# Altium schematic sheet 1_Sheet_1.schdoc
size 302 x 215 mm; Name: A_A4; Symbol: A_A4; Device: A_A4; @Project Name: BLDC_Feb25_uC; REV: 1.0; Date: 2024-06-12; Sheet: 1/1; Draw By: tabahi; Company: github.com/tabahi/eBike-Controller; Convert to PCB: yes; Add into BOM: yes; @Page No: 1; @Page Count: 1; @Schematic Name: mosfets_drive_uC; @Board Name: MOSFETS_drive; @Update Date: 2025-04-16; @Create Time: 07:37:43; @Update Time: 03:45:01; @Page Name: Sheet_1; @Create Date: 2025-02-03
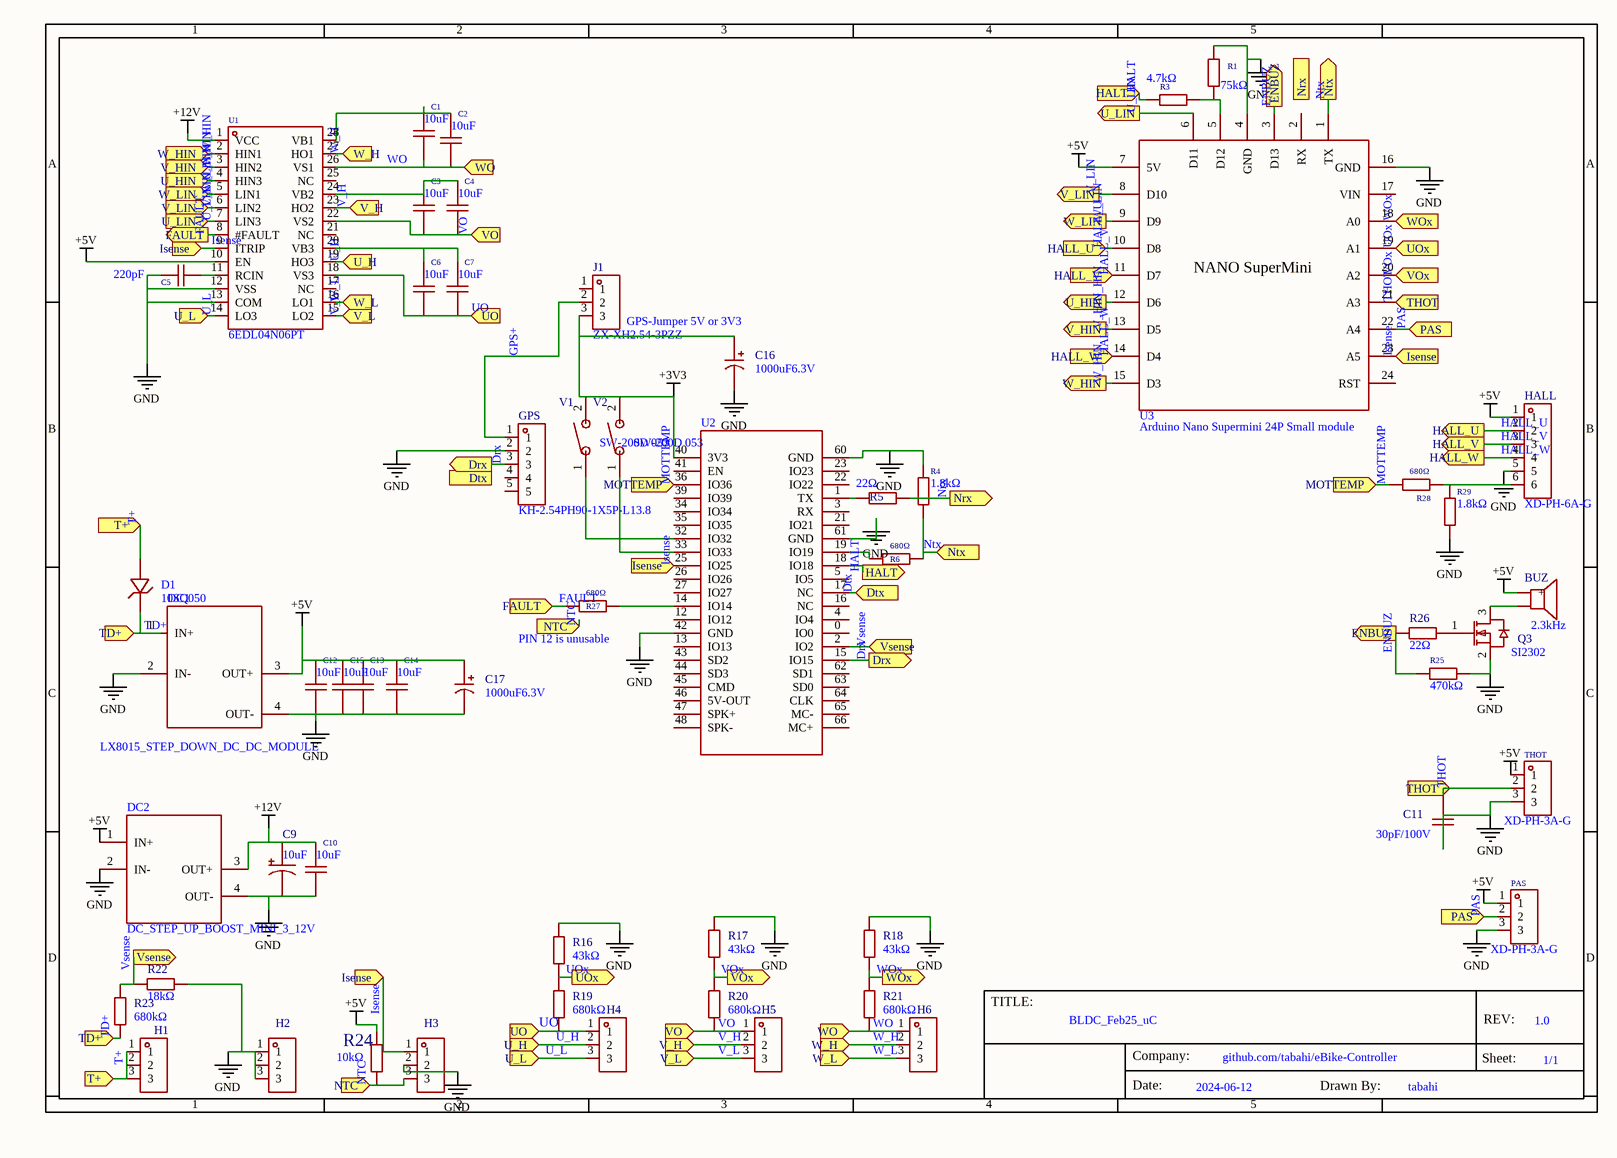
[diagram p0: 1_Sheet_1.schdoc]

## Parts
BUZ  2.3kHz  [BUZ-TH_BD12.0-P7.60-D0.6-FD]
C1  10uF  [C1210]
C2  10uF  [C1210]
C3  10uF  [C1210]
C4  10uF  [C1210]
C5  220pF  [C0805]
C6  10uF  [C1210]
C7  10uF  [C1210]
C9  10uF  [CAP-TH_BD5.0-P2.00-D0.8-FD]
C10  10uF  [C1210]
C11  30pF/100V  [C0805]
C12  10uF  [C1210]
C13  10uF  [C1210]
C14  10uF  [C1210]
C15  10uF  [C1210]
C16  1000uF6.3V  [CAP-TH_BD8.0-P3.50-D0.6-FD]
C17  1000uF6.3V  [CAP-TH_BD8.0-P3.50-D0.6-FD]
D1  10SQ050  [R-6_BD8.9-L8.9-P12.90-D1.3-RD]
DC1  LX8015_STEP_DOWN_DC_DC_MODULE  [LX8015_STEP_DOWN_DC_DC_MODULE]
DC2  DC_STEP_UP_BOOST_MINI_3_12V  [DC_STEP_UP_BOOST_MINI_3_12V]
GPS  KH-2.54PH90-1X5P-L13.8  [HDR-TH_5P-P2.54-H-M-W10.4-N]
H1  PZ254-1-03-Z-8.5  [HDR-TH_03P-P2.54-V-M]  (value not drawn)
H2  PZ254-1-03-Z-8.5  [HDR-TH_03P-P2.54-V-M]  (value not drawn)
H3  PZ254-1-03-Z-8.5  [HDR-TH_03P-P2.54-V-M]  (value not drawn)
H4  PZ254-1-03-Z-8.5  [HDR-TH_03P-P2.54-V-M]  (value not drawn)
H5  PZ254-1-03-Z-8.5  [HDR-TH_03P-P2.54-V-M]  (value not drawn)
H6  PZ254-1-03-Z-8.5  [HDR-TH_03P-P2.54-V-M]  (value not drawn)
HALL  XD-PH-6A-G  [CONN-TH_PH-6A_C722783]
J1  ZX-XH2.54-3PZZ  [CONN-TH_3P-P2.54_2501S-3P]
PAS  XD-PH-3A-G  [CONN-TH_3P-P2.00_PH-3AK]
Q3  SI2302  [SOT-23_L2.9-W1.3-P1.90-LS2.4-BR]
R1  75kΩ  [R0603]
R3  4.7kΩ  [R0603]
R4  1.8kΩ  [R0603]
R5  22Ω  [R0603]
R6  680Ω  [R0603]
R16  43kΩ  [R0805]
R17  43kΩ  [R0805]
R18  43kΩ  [R0805]
R19  680kΩ  [R0805]
R20  680kΩ  [R0805]
R21  680kΩ  [R0805]
R22  18kΩ  [R0805]
R23  680kΩ  [R0805]
R24  10kΩ  [R0603]
R25  470kΩ  [R0603]
R26  22Ω  [R0603]
R27  680Ω  [R0603]
R28  680Ω  [R0603]
R29  1.8kΩ  [R0603]
THOT  XD-PH-3A-G  [CONN-TH_3P-P2.00_PH-3AK]
U1  6EDL04N06PT  [PG-DSO-28_L18.2-W7.6-P1.27-LS10.3-BL]
U2  (no value)  [LILYLGO_ESO32_SIM800L]
U3  Arduino Nano Supermini 24P Small module  [ARDUINO_NANO_SUPERMINI]
V1  SW-200D 053  [SW-TH_BD3.6-L10.6-LS12.6-D0.4]
V2  SW-200D 053  [SW-TH_BD3.6-L10.6-LS12.6-D0.4]

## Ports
Drx (out), Dtx (in), ENBUZ (out), FAULT (in), FAULT (out), HALL_U (in), HALL_U (out), HALL_V (in), HALL_V (out), HALL_W (in), HALL_W (out), HALT (in), HALT (out), Isense (in), MOTTEMP (in), Nrx (in), Nrx (out), NTC (in), Ntx (in), Ntx (out), PAS (in), T+ (in), TD+ (in), THOT (in), U_H (in), U_HIN (in), U_HIN (out), U_L (in), U_LIN (in), U_LIN (out), UO (in), UOx (in), UOx (out), V_H (in), V_HIN (in), V_HIN (out), V_L (in), V_LIN (in), V_LIN (out), VO (in), VOx (in), VOx (out), Vsense (in), Vsense (out), W_H (in), W_HIN (in), W_HIN (out), W_L (in), W_LIN (in), W_LIN (out), WO (in), WOx (in), WOx (out)

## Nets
+3V3: C16.1 J1.3 U2.40(3V3) V1.2 V2.2
+5V: BUZ.1(+) C12.2 C13.2 C14.2 C15.2 C17.1 DC1.3(OUT+) DC2.1(IN+) HALL.1 PAS.1 R24.1 THOT.1 U1.10(EN) U3.7(5V)
+12V: C9.1 C10.2 DC2.3(OUT+) U1.1(VCC)
GND: C5.1 C9.2 C10.1 C11.2 C12.1 C13.1 C14.1 C15.1 C16.2 C17.2 DC1.2(IN-) DC1.4(OUT-) DC2.2(IN-) DC2.4(OUT-) GPS.2 H2.1 H2.2 H2.3 H3.2 HALL.5 PAS.3 Q3.2(S) R1.2 R4.1 R16.2 R17.2 R18.2 R22.2 R25.2 R29.2 THOT.3 U1.12(VSS) U1.13(COM) U2.42(GND) U2.60(GND) U2.61(GND) U3.4(GND) U3.16(GND)
Drx: GPS.3 U2.15(IO15) ; port Drx
Dtx: U2.17(NC) ; port Dtx
ENBUZ: R25.1 R26.1 U3.3(D13) ; port ENBUZ
FAULT: R27.2 U1.8(#FAULT) ; port FAULT
GPS+: GPS.1 J1.2
HALL_U: HALL.2 U3.10(D8) ; port HALL_U
HALL_V: HALL.3 U3.11(D7) ; port HALL_V
HALL_W: HALL.4 U3.14(D4) ; port HALL_W
HALT: R3.1 U2.18(IO18) ; port HALT
Isense: H3.1 U1.9(ITRIP) U2.25(IO25) U3.23(A5) ; port Isense
MOTTEMP: R28.2 U2.36(IO36) ; port MOTTEMP
Nrx: R5.2 ; port Nrx
NTC: H3.3 R24.2 ; port NTC
Ntx: R4.2 R6.1 U3.1(TX) ; port Ntx
PAS: PAS.2 U3.22(A4) ; port PAS
T+: D1.2(A) H1.1 H1.2 H1.3 ; port T+
TD+: D1.1(C) DC1.1(IN+) R23.1 ; port TD+
THOT: C11.1 THOT.2 U3.21(A3) ; port THOT
U_H: H4.2 U1.19(HO3) ; port U_H
U_HIN: U1.4(HIN3) U3.12(D6) ; port U_HIN
U_L: H4.3 U1.14(LO3) ; port U_L
U_LIN: U1.7(LIN3) U3.6(D11) ; port U_LIN
UO: C6.1 C7.1 H4.1 R19.1 U1.18(VS3) ; port UO
UOx: R16.1 R19.2 U3.19(A1) ; port UOx
V_H: H5.2 U1.23(HO2) ; port V_H
V_HIN: U1.3(HIN2) U3.13(D5) ; port V_HIN
V_L: H5.3 U1.15(LO2) ; port V_L
V_LIN: U1.6(LIN2) U3.8(D10) ; port V_LIN
VO: C3.1 C4.1 H5.1 R20.1 U1.22(VS2) ; port VO
VOx: R17.1 R20.2 U3.20(A2) ; port VOx
Vsense: R22.1 R23.2 U2.2(IO2) ; port Vsense
W_H: H6.2 U1.27(HO1) ; port W_H
W_HIN: U1.2(HIN1) U3.15(D3) ; port W_HIN
W_L: H6.3 U1.16(LO1) ; port W_L
W_LIN: U1.5(LIN1) U3.9(D9) ; port W_LIN
WO: C1.1 C2.1 H6.1 R21.1 U1.26(VS1) ; port WO
WOx: R18.1 R21.2 U3.18(A0) ; port WOx
NetBUZ_2: BUZ.2 Q3.3(D)
NetC1_2: C1.2 C2.2 U1.28(VB1)
NetC3_2: C3.2 C4.2 U1.24(VB2)
NetC5_2: C5.2 U1.11(RCIN)
NetC6_2: C6.2 C7.2 U1.20(VB3)
NetHALL_6: HALL.6 R28.1 R29.1
NetQ3_1: Q3.1(G) R26.2
NetR1_1: R1.1 R3.2 U3.5(D12)
NetR5_1: R5.1 U2.1(TX)
NetR6_2: R6.2 U2.19(IO19)
NetR27_1: R27.1 U2.14(IO14)
NetU2_32: U2.32(IO32) V1.1
NetU2_33: U2.33(IO33) V2.1

Not connected (* = marked no-connect by the designer): GPS 4 5; J1 1; U1 17(NC) 21(NC) 25(NC); U2 0(IO0) 3(RX) 4(IO4) 5(IO5) 12(IO12) 13(IO13) 16(NC) 21(IO21) 22(IO22) 23(IO23) 26(IO26) 27(IO27) 34(IO34) 35(IO35) 39(IO39) 41(EN) 43(SD2) 44(SD3) 45(CMD) 46(5V-OUT) 47(SPK+) 48(SPK-) 62(SD1) 63(SD0) 64(CLK) 65(MC-) 66(MC+); U3 2(RX) 17(VIN) 24(RST)

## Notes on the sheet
- GPS-Jumper 5V or 3V3
- (near R27) PIN 12 is unusable

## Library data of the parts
BUZ = HMB1275-05B: Manufacturer: 华能; Add into BOM: yes; Oscillator Circuit: 有源(内含驱动线路); Technology Type: 电磁式; Operating Voltage: 4V~8V; Sound Pressure Level (SPL): 85dB@5V,10cm
C1-C4 C6 C7 C10 C12-C15 = 10uF(106) 50V: Manufacturer: SAMSUNG(三星); Symbol: 10UF(106)-50V; Add into BOM: yes; Tolerance: ±20%
C5 = CC0805KRX7R9BB221: Manufacturer: YAGEO(国巨); Add into BOM: yes; Tolerance: ±10%
C9 = RL1J100MC110A00CV0: Manufacturer: HUAWEI(华威集团); Add into BOM: yes; Tolerance: ±20%; Ripple Current: 60mA@120Hz; Lifetime @ Temp: 2000hrs@105℃
C11 = 30pF/100V: Add into BOM: yes
C16 C17 = ERR1CM681F12B35T: Manufacturer: AISHI(艾华集团); Add into BOM: yes; Tolerance: -20%~+20%
D1 = 10SQ050: Manufacturer: SMC(桑德斯); Add into BOM: yes; Forward Voltage (Vf@If): 550mV@10A; Reverse Voltage (Vr): 50V; Average Rectified Current (Io): 10A; Reverse Leakage Current (Ir): 1mA@50V
DC1 = LX8015_STEP_DOWN_DC_DC_MODULE: Add into BOM: yes; _: 3
DC2 = DC_STEP_UP_BOOST_MINI_3_12V: Add into BOM: yes; _: 3
GPS = KH-2.54PH90-1X5P-L13.8: Manufacturer: kinghelm(金航标); Add into BOM: yes; Pin Structure: 1x5P; Pitch: 2.54mm; Circluar Pins/Square Pins: Square Pins; Current Rating (Max): 3A
H1-H6 = PZ254-1-03-Z-8.5: Manufacturer: HCTL(华灿天禄); Add into BOM: yes
HALL = XD-PH-6A-G: Manufacturer: XUNDA(讯答); Add into BOM: yes; Pins Structure: 1x6P; Pitch: 2mm; Reference Series: PH; Number of PINs Per Row: 6; Current Rating (Max): 2A
J1 = ZX-XH2.54-3PZZ: Manufacturer: Megastar(兆星); Add into BOM: yes; Pins Structure: 1x3P; Pitch: 2.5mm; Reference Series: XH; Number of PINs Per Row: 3; Rated Current: 3A; Rated Voltage (Max): 250V; Plastic Material: PA66; Flame Retardant Rating: UL94V-0; Z-Height of the Board: 7mm; X-Length of Bottom Edge on Board (Spacing Line): 10mm; Y-Width of Bottom Edge on Board: 5.9mm
PAS THOT = XD-PH-3A-G: Manufacturer: XUNDA(讯答); Add into BOM: yes; Pins Structure: 1x3P; Pitch: 2mm; Reference Series: PH; Number of PINs Per Row: 3; Current Rating (Max): 2A
Q3 = SI2302: Manufacturer: GOODWORK(固得沃克); Symbol: SI2302_C2938373; Add into BOM: yes; Drain Source On Resistance (RDS(on)@Vgs,Id): 25mΩ@4.5V,3.6A; Gate Threshold Voltage (Vgs(th)@Id): 700mV@250uA; Total Gate Charge (Qg@Vgs): 5.4nC@4.5V; Input Capacitance (Ciss@Vds): 300pF@10V; Reverse Transfer Capacitance (Crss@Vds): 120pF@10V
R1 = 0603WAF7502T5E: Manufacturer: UNI-ROYAL(厚声); Add into BOM: yes; Tolerance: ±1%; Temperature Coefficient: ±100ppm/℃
R3 = 0603WAF4701T5E: Manufacturer: UNI-ROYAL(厚声); Add into BOM: yes; Tolerance: ±1%; Temperature Coefficient: ±100ppm/℃
R4 R29 = 0603WAF1801T5E: Manufacturer: UNI-ROYAL(厚声); Add into BOM: yes; Tolerance: ±1%; Temperature Coefficient: ±100ppm/℃
R5 R26 = 0603WAF220JT5E: Manufacturer: UNI-ROYAL(厚声); Add into BOM: yes; Tolerance: ±1%; Temperature Coefficient: ±100ppm/℃
R6 R27 R28 = 0603WAF6800T5E: Manufacturer: UNI-ROYAL(厚声); Add into BOM: yes; Tolerance: ±1%; Temperature Coefficient: ±100ppm/℃
R16-R18 = AECR0805F43K0K9: Manufacturer: RESI(开步睿思); Add into BOM: yes; Tolerance: ±1%; Temperature Coefficient: ±100ppm/℃
R19-R21 R23 = AECR0805F680KK9: Manufacturer: RESI(开步睿思); Add into BOM: yes; Tolerance: ±1%; Temperature Coefficient: ±100ppm/℃
R22 = CR0805-FX-1802ELF: Manufacturer: BOURNS; Add into BOM: yes; Tolerance: ±1%; Temperature Coefficient: ±100ppm/℃
R24 = 0603WAF1002T5E: Manufacturer: UNI-ROYAL(厚声); Add into BOM: yes; Tolerance: ±1%; Temperature Coefficient: ±100ppm/℃
R25 = 0603WAF4703T5E: Manufacturer: UNI-ROYAL(厚声); Add into BOM: yes; Tolerance: ±1%; Temperature Coefficient: ±100ppm/℃
U1 = 6EDL04N06PT: Manufacturer: Infineon(英飞凌); Add into BOM: yes
U2 = LILYGO_ESP32_SIM800: Add into BOM: yes
U3 = Arduino Nano Supermini 24P Small module: Add into BOM: yes
V1 V2 = SW-200D 053: Manufacturer: SHOU HAN(首韩); Add into BOM: yes; Rated Voltage: 12V; Rated Current: 2mA; Temperature Resistance: +40℃~+81℃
